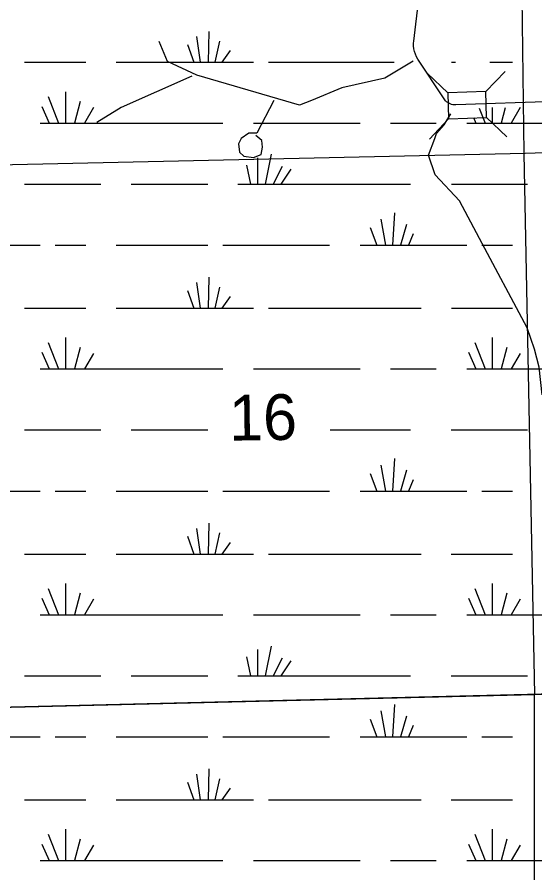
# Model space of a CAD drawing. Extents: x 2480962 to 2688785, y 277103 to 599240.
# Drawn here: x 2591113 to 2596212, y 512018 to 520441 of the extents above; entities that cross this region are included whole.
import ezdxf

# ---------------------------------------------------------------- set-up
doc = ezdxf.new("R2010")
doc.units = 0
for name, color, linetype in [('National Forest', 7, 'Continuous'), ('Section Lines', 7, 'Continuous'), ('Section Numbers', 7, 'Continuous'), ('Swamps', 7, 'Continuous'), ('Uninventoried Roads and Features', 7, 'Continuous')]:
    doc.layers.add(name, color=color, linetype=linetype)

msp = doc.modelspace()

# ---------------------------------------------------------------- linework, layer by layer
at = {"layer": 'National Forest'}
msp.add_line((2599077.417, 513844.57), (2564631.794, 513006.26), dxfattribs=at)
at = {"layer": 'Section Lines'}
for p, q in [((2596106.677, 519098.492), (2596036.943, 524512.68)), ((2601560.739, 519271.305), (2596114.495, 519098.663)), ((2596114.495, 519098.663), (2590762.203, 518981.44)), ((2596210.704, 513773.713), (2596106.677, 519098.492)), ((2596208.279, 513773.654), (2601531.032, 513903.568)), ((2590758.829, 513640.647), (2596210.704, 513773.713)), ((2596210.86, 508570.35), (2596208.279, 513773.654))]:
    msp.add_line(p, q, dxfattribs=at)
at = {"layer": 'Swamps'}
for points in [[(2592880.089, 520248.395), (2592917.341, 519996.021)], [(2593002.588, 520300.365), (2592995.091, 519996.022)], [(2592791.09, 520170.457), (2592854.091, 519996.02)], [(2593106.589, 520203.867), (2593061.841, 519996.023)], [(2593210.34, 520111.088), (2593128.841, 519996.024)], [(2591187.593, 519996.026), (2591788.842, 519996.035)], [(2592089.592, 519996.009), (2592854.091, 519996.02)], [(2592854.091, 519996.02), (2592917.341, 519996.021)], [(2592917.341, 519996.021), (2592995.091, 519996.022)], [(2592995.091, 519996.022), (2593061.841, 519996.023)], [(2593061.841, 519996.023), (2593128.841, 519996.024)], [(2593128.841, 519996.024), (2593440.591, 519996.029)], [(2593589.091, 519996.031), (2594824.84, 519996.019)], [(2595389.089, 519996.028), (2595429.839, 519996.028)], [(2595767.589, 519996.033), (2595990.339, 519996.006)], [(2591417.847, 519658.281), (2591521.599, 519398.502)], [(2591588.596, 519706.533), (2591588.599, 519398.503)], [(2591733.347, 519610.036), (2591677.599, 519398.474)], [(2591358.348, 519561.78), (2591428.849, 519398.501)], [(2591866.847, 519550.663), (2591777.849, 519398.475)], [(2595663.594, 519543.22), (2595723.096, 519398.472)], [(2595789.844, 519550.66), (2595789.846, 519398.473)], [(2595919.844, 519546.943), (2595878.846, 519398.474)], [(2596068.094, 519550.665), (2595979.096, 519398.476)], [(2595608.095, 519454.158), (2595630.346, 519398.471)], [(2591339.85, 519398.5), (2591428.849, 519398.501)], [(2591428.849, 519398.501), (2591521.599, 519398.502)], [(2591521.599, 519398.502), (2591588.599, 519398.503)], [(2591588.599, 519398.503), (2591677.599, 519398.474)], [(2591677.599, 519398.474), (2591777.849, 519398.475)], [(2591777.849, 519398.475), (2593139.848, 519398.496)], [(2593440.598, 519398.5), (2594490.847, 519398.485)], [(2594791.597, 519398.49), (2595240.596, 519398.497)], [(2595541.096, 519398.501), (2595630.346, 519398.471)], [(2595630.346, 519398.471), (2595723.096, 519398.472)], [(2595723.096, 519398.472), (2595789.846, 519398.473)], [(2595789.846, 519398.473), (2595878.846, 519398.474)], [(2595878.846, 519398.474), (2595979.096, 519398.476)], [(2595979.096, 519398.476), (2597341.344, 519398.496)], [(2593614.851, 519090.441), (2593555.604, 518797.254)], [(2593373.602, 518982.813), (2593410.855, 518797.252)], [(2593481.352, 519057.033), (2593481.355, 518797.253)], [(2593722.602, 518971.662), (2593633.604, 518797.225)], [(2593807.853, 518945.695), (2593711.354, 518797.226)], [(2591187.607, 518797.25), (2591937.356, 518797.23)], [(2592238.106, 518797.235), (2592991.355, 518797.246)], [(2593288.355, 518797.25), (2593410.855, 518797.252)], [(2593410.855, 518797.252), (2593481.355, 518797.253)], [(2593481.355, 518797.253), (2593555.604, 518797.254)], [(2593555.604, 518797.254), (2593633.604, 518797.225)], [(2593633.604, 518797.225), (2593711.354, 518797.226)], [(2593711.354, 518797.226), (2594988.103, 518797.245)], [(2595389.103, 518797.251), (2596138.852, 518797.231)], [(2594828.606, 518515.181), (2594810.11, 518195.995)], [(2594694.857, 518452.085), (2594739.61, 518195.994)], [(2594947.358, 518400.121), (2594887.86, 518195.996)], [(2594591.108, 518370.428), (2594654.11, 518195.993)], [(2595014.109, 518307.341), (2594965.86, 518195.997)], [(2590764.614, 518195.996), (2591339.863, 518196.004)], [(2591488.363, 518196.006), (2591788.863, 518195.98)], [(2592089.613, 518195.985), (2592991.362, 518195.998)], [(2593139.862, 518196.001), (2594190.111, 518195.985)], [(2594490.86, 518195.99), (2594654.11, 518195.993)], [(2594654.11, 518195.993), (2594739.61, 518195.994)], [(2594739.61, 518195.994), (2594810.11, 518195.995)], [(2594810.11, 518195.995), (2594887.86, 518195.996)], [(2594887.86, 518195.996), (2594965.86, 518195.997)], [(2594965.86, 518195.997), (2595541.109, 518196.006)], [(2595689.609, 518195.976), (2595990.359, 518195.981)], [(2592880.116, 517828.56), (2592917.119, 517576.187)], [(2593002.615, 517880.531), (2592995.119, 517576.188)], [(2592791.117, 517750.622), (2592854.119, 517576.186)], [(2593106.616, 517784.033), (2593061.869, 517576.189)], [(2593210.367, 517691.254), (2593128.869, 517576.19)], [(2591187.62, 517576.192), (2591788.87, 517576.201)], [(2592089.62, 517576.174), (2592854.119, 517576.186)], [(2592854.119, 517576.186), (2592917.119, 517576.187)], [(2592917.119, 517576.187), (2592995.119, 517576.188)], [(2592995.119, 517576.188), (2593061.869, 517576.189)], [(2593061.869, 517576.189), (2593128.869, 517576.19)], [(2593128.869, 517576.19), (2593440.618, 517576.195)], [(2593588.868, 517576.197), (2595092.117, 517576.189)], [(2595389.116, 517576.193), (2595990.366, 517576.171)], [(2591417.874, 517238.447), (2591521.627, 516978.668)], [(2591588.623, 517286.7), (2591588.627, 516978.669)], [(2595619.12, 517238.448), (2595723.123, 516978.639)], [(2595789.869, 517286.7), (2595789.873, 516978.64)], [(2591358.375, 517141.947), (2591428.877, 516978.666)], [(2591733.374, 517190.202), (2591677.627, 516978.639)], [(2591866.875, 517130.829), (2591777.877, 516978.641)], [(2595559.621, 517141.947), (2595630.373, 516978.637)], [(2595934.62, 517190.203), (2595878.873, 516978.641)], [(2596068.121, 517130.83), (2595979.123, 516978.642)], [(2591339.877, 516978.665), (2591428.877, 516978.666)], [(2591428.877, 516978.666), (2591521.627, 516978.668)], [(2591521.627, 516978.668), (2591588.627, 516978.669)], [(2591588.627, 516978.669), (2591677.627, 516978.639)], [(2591677.627, 516978.639), (2591777.877, 516978.641)], [(2591777.877, 516978.641), (2593139.875, 516978.661)], [(2593440.625, 516978.666), (2594490.874, 516978.651)], [(2594791.374, 516978.655), (2595240.623, 516978.662)], [(2595541.123, 516978.667), (2595630.373, 516978.637)], [(2595630.373, 516978.637), (2595723.123, 516978.639)], [(2595723.123, 516978.639), (2595789.873, 516978.64)], [(2595789.873, 516978.64), (2595878.873, 516978.641)], [(2595878.873, 516978.641), (2595979.123, 516978.642)], [(2595979.123, 516978.642), (2597341.121, 516978.663)], [(2591187.634, 516377.415), (2591937.383, 516377.395)], [(2592237.883, 516377.4), (2592991.382, 516377.411)], [(2594196.903, 516377.399), (2594988.13, 516377.411)], [(2595388.88, 516377.417), (2596138.629, 516377.397)], [(2594694.885, 516032.252), (2594739.387, 515776.159)], [(2594828.634, 516095.346), (2594810.137, 515776.16)], [(2594591.136, 515950.593), (2594654.137, 515776.158)], [(2594947.385, 515980.287), (2594887.887, 515776.162)], [(2595014.136, 515887.507), (2594965.887, 515776.163)], [(2590764.642, 515776.161), (2591339.891, 515776.17)], [(2591488.391, 515776.172), (2591788.89, 515776.145)], [(2592089.64, 515776.15), (2592991.389, 515776.164)], [(2593139.889, 515776.166), (2594190.138, 515776.151)], [(2594490.888, 515776.156), (2594654.137, 515776.158)], [(2594654.137, 515776.158), (2594739.387, 515776.159)], [(2594739.387, 515776.159), (2594810.137, 515776.16)], [(2594810.137, 515776.16), (2594887.887, 515776.162)], [(2594887.887, 515776.162), (2594965.887, 515776.163)], [(2594965.887, 515776.163), (2595541.136, 515776.172)], [(2595689.636, 515776.143), (2595990.136, 515776.147)], [(2593002.643, 515460.696), (2592995.146, 515156.354)], [(2592880.143, 515408.726), (2592917.146, 515156.353)], [(2593106.394, 515364.198), (2593061.896, 515156.355)], [(2592790.894, 515330.787), (2592854.146, 515156.352)], [(2593210.395, 515271.419), (2593128.646, 515156.356)], [(2591187.648, 515156.358), (2591788.897, 515156.367)], [(2592089.647, 515156.34), (2592854.146, 515156.352)], [(2592854.146, 515156.352), (2592917.146, 515156.353)], [(2592917.146, 515156.353), (2592995.146, 515156.354)], [(2592995.146, 515156.354), (2593061.896, 515156.355)], [(2593061.896, 515156.355), (2593128.646, 515156.356)], [(2593128.646, 515156.356), (2593440.396, 515156.361)], [(2593588.896, 515156.363), (2595092.144, 515156.354)], [(2595388.894, 515156.359), (2595990.143, 515156.337)], [(2591588.401, 514866.865), (2591588.405, 514558.835)], [(2595789.896, 514866.866), (2595789.9, 514558.805)], [(2591417.902, 514818.612), (2591521.655, 514558.834)], [(2591733.152, 514770.367), (2591677.654, 514558.804)], [(2595619.147, 514818.614), (2595722.9, 514558.804)], [(2595934.647, 514770.369), (2595878.9, 514558.807)], [(2591358.403, 514722.112), (2591428.905, 514558.833)], [(2591866.902, 514710.995), (2591777.904, 514558.806)], [(2595559.648, 514722.113), (2595630.15, 514558.803)], [(2596068.148, 514710.996), (2595979.15, 514558.808)], [(2591339.905, 514558.831), (2591428.905, 514558.833)], [(2591428.905, 514558.833), (2591521.655, 514558.834)], [(2591521.655, 514558.834), (2591588.405, 514558.835)], [(2591588.405, 514558.835), (2591677.654, 514558.804)], [(2591677.654, 514558.804), (2591777.904, 514558.806)], [(2591777.904, 514558.806), (2593139.903, 514558.827)], [(2593440.402, 514558.831), (2594490.901, 514558.816)], [(2594791.401, 514558.821), (2595240.65, 514558.828)], [(2595541.15, 514558.832), (2595630.15, 514558.803)], [(2595630.15, 514558.803), (2595722.9, 514558.804)], [(2595722.9, 514558.804), (2595789.9, 514558.805)], [(2595789.9, 514558.805), (2595878.9, 514558.807)], [(2595878.9, 514558.807), (2595979.15, 514558.808)], [(2595979.15, 514558.808), (2597341.148, 514558.829)], [(2593481.406, 514217.365), (2593481.409, 513957.584)], [(2593614.906, 514250.773), (2593555.659, 513957.585)], [(2593373.657, 514143.145), (2593410.909, 513957.583)], [(2593722.657, 514131.994), (2593633.409, 513957.556)], [(2593807.907, 514106.027), (2593711.409, 513957.557)], [(2591187.662, 513957.581), (2591937.411, 513957.561)], [(2592237.911, 513957.565), (2592991.41, 513957.577)], [(2593288.409, 513957.581), (2593410.909, 513957.583)], [(2593410.909, 513957.583), (2593481.409, 513957.584)], [(2593481.409, 513957.584), (2593555.659, 513957.585)], [(2593555.659, 513957.585), (2593633.409, 513957.556)], [(2593633.409, 513957.556), (2593711.409, 513957.557)], [(2593711.409, 513957.557), (2594988.158, 513957.576)], [(2595388.907, 513957.582), (2596138.656, 513957.563)], [(2594828.661, 513675.513), (2594809.914, 513356.326)], [(2594694.912, 513612.417), (2594739.415, 513356.325)], [(2594590.913, 513530.76), (2594654.165, 513356.324)], [(2594947.412, 513560.452), (2594887.914, 513356.327)], [(2595014.163, 513467.673), (2594965.914, 513356.328)], [(2590764.669, 513356.327), (2591339.919, 513356.336)], [(2591488.168, 513356.338), (2591788.918, 513356.311)], [(2592089.418, 513356.315), (2592991.417, 513356.329)], [(2593139.916, 513356.331), (2594190.165, 513356.316)], [(2594490.915, 513356.321), (2594654.165, 513356.324)], [(2594654.165, 513356.324), (2594739.415, 513356.325)], [(2594739.415, 513356.325), (2594809.914, 513356.326)], [(2594809.914, 513356.326), (2594887.914, 513356.327)], [(2594887.914, 513356.327), (2594965.914, 513356.328)], [(2594965.914, 513356.328), (2595541.164, 513356.337)], [(2595689.663, 513356.308), (2595990.163, 513356.313)], [(2593002.67, 513040.863), (2592995.174, 512736.52)], [(2592880.171, 512988.892), (2592917.174, 512736.518)], [(2593106.421, 512944.365), (2593061.924, 512736.521)], [(2592790.922, 512910.953), (2592854.174, 512736.517)], [(2593210.422, 512851.584), (2593128.673, 512736.522)], [(2591187.676, 512736.523), (2591788.925, 512736.532)], [(2592089.425, 512736.506), (2592854.174, 512736.517)], [(2592854.174, 512736.517), (2592917.174, 512736.518)], [(2592917.174, 512736.518), (2592995.174, 512736.52)], [(2592995.174, 512736.52), (2593061.924, 512736.521)], [(2593061.924, 512736.521), (2593128.673, 512736.522)], [(2593128.673, 512736.522), (2593440.423, 512736.526)], [(2593588.923, 512736.529), (2595092.171, 512736.521)], [(2595388.921, 512736.525), (2595990.17, 512736.502)], [(2591588.429, 512447.03), (2591588.432, 512139)], [(2595789.924, 512447.033), (2595789.927, 512138.971)], [(2591417.679, 512398.778), (2591521.682, 512138.999)], [(2591733.18, 512350.533), (2591677.682, 512138.971)], [(2595619.174, 512398.78), (2595722.927, 512138.97)], [(2595934.674, 512350.535), (2595878.927, 512138.972)], [(2591358.431, 512302.277), (2591428.932, 512138.998)], [(2591866.93, 512291.16), (2591777.682, 512138.972)], [(2595559.675, 512302.28), (2595630.177, 512138.968)], [(2596068.175, 512291.162), (2595979.177, 512138.974)], [(2591339.932, 512138.997), (2591428.932, 512138.998)], [(2591428.932, 512138.998), (2591521.682, 512138.999)], [(2591521.682, 512138.999), (2591588.432, 512139)], [(2591588.432, 512139), (2591677.682, 512138.971)], [(2591677.682, 512138.971), (2591777.682, 512138.972)], [(2591777.682, 512138.972), (2593139.93, 512138.993)], [(2593440.43, 512138.998), (2594490.929, 512138.982)], [(2594791.428, 512138.986), (2595240.428, 512138.993)], [(2595541.177, 512138.998), (2595630.177, 512138.968)], [(2595630.177, 512138.968), (2595722.927, 512138.97)], [(2595722.927, 512138.97), (2595789.927, 512138.971)], [(2595789.927, 512138.971), (2595878.927, 512138.972)], [(2595878.927, 512138.972), (2595979.177, 512138.974)], [(2595979.177, 512138.974), (2597341.175, 512138.995)]]:
    msp.add_lwpolyline(points, dxfattribs=at)
at = {"layer": 'Uninventoried Roads and Features'}
for p, q in [((2595018.632, 520202.743), (2595068.066, 520623.962)), ((2595317.346, 519636.506), (2595060.344, 520026.783)), ((2595729.555, 519706.973), (2595918.503, 519906.721)), ((2595354.7, 519696.556), (2595154.952, 519885.504)), ((2595729.555, 519706.973), (2595354.7, 519696.556)), ((2595354.7, 519696.556), (2595361.811, 519440.655)), ((2597824.492, 519658.756), (2595433.062, 519576.693)), ((2595736.666, 519451.072), (2595729.555, 519706.973)), ((2595361.811, 519440.655), (2595172.864, 519240.907)), ((2595361.811, 519440.655), (2595736.666, 519451.072)), ((2595735.287, 519452.376), (2595935.036, 519263.428))]:
    msp.add_line(p, q, dxfattribs=at)
for points in [[(2595012.88, 520005.877), (2594733.383, 519839.66), (2594311.476, 519745.681), (2594011.767, 519619.572), (2593893.343, 519572.635), (2592883.99, 519869.541), (2592595.541, 520004.287), (2592513.829, 520201.376)], [(2595060.344, 520026.783), (2595046.376, 520050.626), (2595034.976, 520075.797), (2595026.269, 520102.023), (2595020.352, 520129.014), (2595017.289, 520156.476), (2595017.113, 520184.109), (2595018.632, 520202.743)], [(2592834.075, 519860.75), (2592137.696, 519550.47), (2591898.212, 519404.416)], [(2593639.72, 519619.325), (2593473.699, 519299.169), (2593394.701, 519297.477), (2593318.802, 519245.659), (2593292.998, 519194.914), (2593302.642, 519112.11), (2593345.978, 519072.498), (2593442.676, 519059.126), (2593517.144, 519089.679), (2593528.964, 519161.36), (2593523.625, 519224.95), (2593464.65, 519273.879), (2593464.65, 519273.879)], [(2595433.062, 519576.693), (2595419.134, 519576.944), (2595405.308, 519578.65), (2595391.737, 519581.792), (2595378.568, 519586.335), (2595365.946, 519592.23), (2595354.01, 519599.412), (2595342.89, 519607.802), (2595332.708, 519617.309), (2595323.575, 519627.828), (2595317.346, 519636.506)], [(2596284.732, 516722.353), (2596253.287, 516995.808), (2596206.754, 517172.414), (2596136.289, 517383.257), (2595666.63, 518261.217), (2595470.995, 518631.538), (2595229.802, 518888.917), (2595165.522, 519082.518), (2595225.322, 519245.959), (2595243.418, 519296.539), (2595318.551, 519381.159), (2595385.438, 519488.767)]]:
    msp.add_lwpolyline(points, dxfattribs=at)

# ---------------------------------------------------------------- texts
at = {"layer": 'Section Numbers'}
msp.add_text('16', height=450, rotation=0.8220444, dxfattribs=at).set_placement((2593202.873, 516271.96))

doc.saveas('drawing.dxf')
